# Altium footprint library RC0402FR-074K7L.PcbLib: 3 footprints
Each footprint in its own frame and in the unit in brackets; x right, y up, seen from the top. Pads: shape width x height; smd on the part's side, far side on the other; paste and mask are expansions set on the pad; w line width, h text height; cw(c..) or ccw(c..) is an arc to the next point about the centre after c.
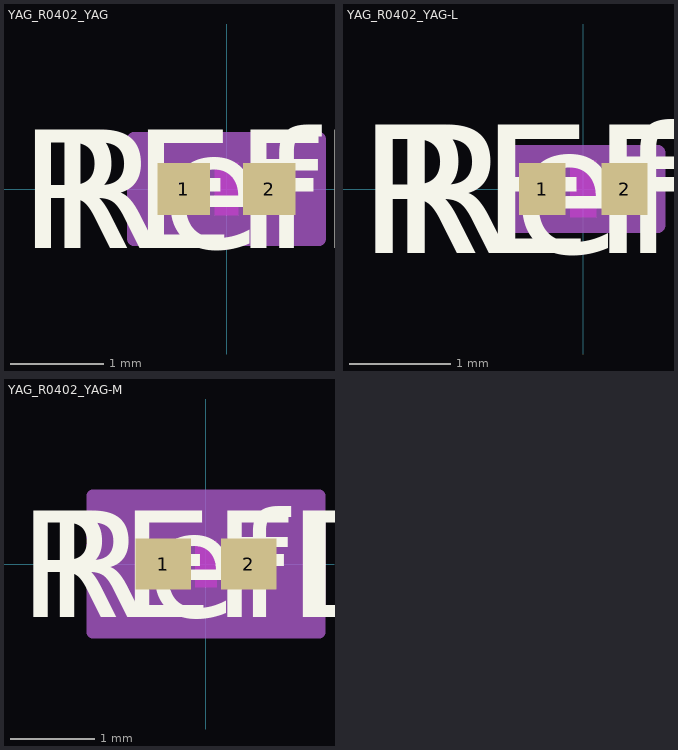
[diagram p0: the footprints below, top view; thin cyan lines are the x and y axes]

## YAG_R0402_YAG [mil]
pads (2):
  rect 22x22 smd paste+0 mask+0: 1(-18,0) 2(18,0)
Top Layer keep-out:
  region: -5,-9 -5,9 5,9 5,-9
Top Overlay:
  text "RefDes" at -75,-25 h50
  text "REFDES" at -87.5,-25 h50
Keep-Out Layer:
  region: -5,-11 -5,11 5,11 5,-11
Mechanical 13:
  lines w1: -21,-11 -21,11 ; -21,-11 -7,-11 -7,11 -21,11 ; -21,-11 21,-11 ; -21,-11 -21,11 ; -21,11 21,11 ; 21,-11 7,-11 7,11 21,11 ; 21,-11 21,11 ; 21,-11 21,11
  text "RefDes2" at -87.5,-25 h50
Mechanical 15:
  region: 39,-21 -39,-21 -39,21 39,21
  lines w6: -39,-21 -39,21 39,21 39,-21 -39,-21
3D body "YAG_R0402_YAG.step": height 15.98, standoff 0, extent -20.98,-10.98 20.98,10.98

## YAG_R0402_YAG-L [mil]
pads (2):
  rect 18x20 smd paste+0 mask+0: 1(-16,0) 2(16,0)
Top Layer keep-out:
  region: -5,-9 -5,9 5,9 5,-9
Top Overlay:
  text "RefDes" at -75,-25 h50
  text "REFDES" at -87.5,-25 h50
Keep-Out Layer:
  region: -5,-11 -5,11 5,11 5,-11
Mechanical 13:
  lines w1: -21,-11 -21,11 ; -21,-11 -7,-11 -7,11 -21,11 ; -21,-11 21,-11 ; -21,-11 -21,11 ; -21,11 21,11 ; 21,-11 7,-11 7,11 21,11 ; 21,-11 21,11 ; 21,-11 21,11
  text "RefDes2" at -87.5,-25 h50
Mechanical 15:
  region: 29,-14 -29,-14 -29,14 29,14
  lines w6: -29,-14 -29,14 29,14 29,-14 -29,-14
3D body "YAG_R0402_YAG.step": height 15.98, standoff 0, extent -20.98,-10.98 20.98,10.98

## YAG_R0402_YAG-M [mil]
pads (2):
  rect 26x24 smd paste+0 mask+0: 1(-20,0) 2(20,0)
Top Layer keep-out:
  region: -5,-9 -5,9 5,9 5,-9
Top Overlay:
  text "RefDes" at -75,-25 h50
  text "REFDES" at -87.5,-25 h50
Keep-Out Layer:
  region: -5,-11 -5,11 5,11 5,-11
Mechanical 13:
  lines w1: -21,-11 -21,11 ; -21,-11 -7,-11 -7,11 -21,11 ; -21,-11 21,-11 ; -21,-11 -21,11 ; -21,11 21,11 ; 21,-11 7,-11 7,11 21,11 ; 21,-11 21,11 ; 21,-11 21,11
  text "RefDes2" at -87.5,-25 h50
Mechanical 15:
  region: 53,-32 -53,-32 -53,32 53,32
  lines w6: -53,-32 -53,32 53,32 53,-32 -53,-32
3D body "YAG_R0402_YAG.step": height 15.98, standoff 0, extent -20.98,-10.98 20.98,10.98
